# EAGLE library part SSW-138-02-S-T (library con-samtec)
THROUGH-HOLE .025" SQ POST SOCKET Source: Samtec SSW.pdf
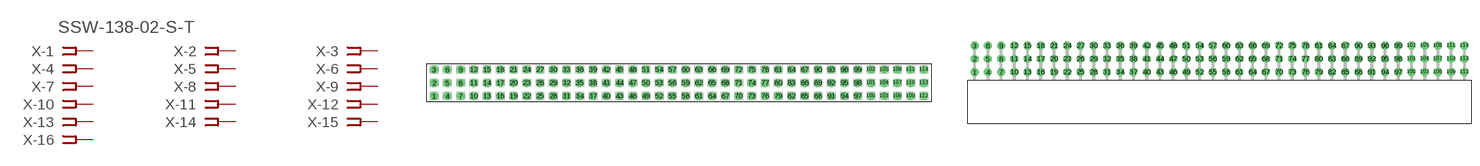
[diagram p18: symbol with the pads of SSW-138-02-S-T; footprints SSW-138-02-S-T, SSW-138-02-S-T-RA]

Designator prefix X; gates -1=FPINV -2=FPIN -3=FPIN -4=FPIN -5=FPIN -6=FPIN -7=FPIN -8=FPIN -9=FPIN -10=FPIN -11=FPIN -12=FPIN -13=FPIN -14=FPIN -15=FPIN -16=FPIN -17=FPIN -18=FPIN -19=FPIN -20=FPIN -21=FPIN -22=FPIN -23=FPIN -24=FPIN -25=FPIN -26=FPIN -27=FPIN -28=FPIN -29=FPIN -30=FPIN -31=FPIN -32=FPIN -33=FPIN -34=FPIN -35=FPIN -36=FPIN -37=FPIN -38=FPIN -39=FPIN -40=FPIN -41=FPIN -42=FPIN -43=FPIN -44=FPIN -45=FPIN -46=FPIN -47=FPIN -48=FPIN -49=FPIN -50=FPIN -51=FPIN -52=FPIN -53=FPIN -54=FPIN -55=FPIN -56=FPIN -57=FPIN -58=FPIN -59=FPIN -60=FPIN -61=FPIN -62=FPIN -63=FPIN -64=FPIN -65=FPIN -66=FPIN -67=FPIN -68=FPIN -69=FPIN -70=FPIN -71=FPIN -72=FPIN -73=FPIN -74=FPIN -75=FPIN -76=FPIN -77=FPIN -78=FPIN -79=FPIN -80=FPIN -81=FPIN -82=FPIN -83=FPIN -84=FPIN -85=FPIN -86=FPIN -87=FPIN -88=FPIN -89=FPIN -90=FPIN -91=FPIN -92=FPIN -93=FPIN -94=FPIN -95=FPIN -96=FPIN -97=FPIN -98=FPIN -99=FPIN -100=FPIN -101=FPIN -102=FPIN -103=FPIN -104=FPIN -105=FPIN -106=FPIN -107=FPIN -108=FPIN -109=FPIN -110=FPIN -111=FPIN -112=FPIN -113=FPIN -114=FPIN

## SSW-138-02-S-T (MPN: SSW-138-02-S-T; OC_FARNELL: unknown; OC_NEWARK: 83P1198)  [SSW-138-02-S-T]
1  -1:1  pas
2  -2:1  pas
3  -3:1  pas
4  -4:1  pas
5  -5:1  pas
6  -6:1  pas
7  -7:1  pas
8  -8:1  pas
9  -9:1  pas
10  -10:1  pas
11  -11:1  pas
12  -12:1  pas
13  -13:1  pas
14  -14:1  pas
15  -15:1  pas
16  -16:1  pas
17  -17:1  pas
18  -18:1  pas
19  -19:1  pas
20  -20:1  pas
21  -21:1  pas
22  -22:1  pas
23  -23:1  pas
24  -24:1  pas
25  -25:1  pas
26  -26:1  pas
27  -27:1  pas
28  -28:1  pas
29  -29:1  pas
30  -30:1  pas
31  -31:1  pas
32  -32:1  pas
33  -33:1  pas
34  -34:1  pas
35  -35:1  pas
36  -36:1  pas
37  -37:1  pas
38  -38:1  pas
39  -39:1  pas
40  -40:1  pas
41  -41:1  pas
42  -42:1  pas
43  -43:1  pas
44  -44:1  pas
45  -45:1  pas
46  -46:1  pas
47  -47:1  pas
48  -48:1  pas
49  -49:1  pas
50  -50:1  pas
51  -51:1  pas
52  -52:1  pas
53  -53:1  pas
54  -54:1  pas
55  -55:1  pas
56  -56:1  pas
57  -57:1  pas
58  -58:1  pas
59  -59:1  pas
60  -60:1  pas
61  -61:1  pas
62  -62:1  pas
63  -63:1  pas
64  -64:1  pas
65  -65:1  pas
66  -66:1  pas
67  -67:1  pas
68  -68:1  pas
69  -69:1  pas
70  -70:1  pas
71  -71:1  pas
72  -72:1  pas
73  -73:1  pas
74  -74:1  pas
75  -75:1  pas
76  -76:1  pas
77  -77:1  pas
78  -78:1  pas
79  -79:1  pas
80  -80:1  pas
81  -81:1  pas
82  -82:1  pas
83  -83:1  pas
84  -84:1  pas
85  -85:1  pas
86  -86:1  pas
87  -87:1  pas
88  -88:1  pas
89  -89:1  pas
90  -90:1  pas
91  -91:1  pas
92  -92:1  pas
93  -93:1  pas
94  -94:1  pas
95  -95:1  pas
96  -96:1  pas
97  -97:1  pas
98  -98:1  pas
99  -99:1  pas
100  -100:1  pas
101  -101:1  pas
102  -102:1  pas
103  -103:1  pas
104  -104:1  pas
105  -105:1  pas
106  -106:1  pas
107  -107:1  pas
108  -108:1  pas
109  -109:1  pas
110  -110:1  pas
111  -111:1  pas
112  -112:1  pas
113  -113:1  pas
114  -114:1  pas

## SSW-138-02-S-TRA (OC_FARNELL: unknown; OC_NEWARK: unknown)  [SSW-138-02-S-T-RA]
Pads as for SSW-138-02-S-T

## Footprint SSW-138-02-S-T (pad centres in mm)
THROUGH-HOLE .025" SQ POST SOCKET Source: Samtec SSW.pdf
drill 1 pad 1.5 octagon: 1 -46.99,-2.54; 2 -46.99,0; 3 -46.99,2.54; 4 -44.45,-2.54; 5 -44.45,0; 6 -44.45,2.54; 7 -41.91,-2.54; 8 -41.91,0; 9 -41.91,2.54; 10 -39.37,-2.54; 11 -39.37,0; 12 -39.37,2.54; 13 -36.83,-2.54; 14 -36.83,0; 15 -36.83,2.54; 16 -34.29,-2.54; 17 -34.29,0; 18 -34.29,2.54; 19 -31.75,-2.54; 20 -31.75,0; 21 -31.75,2.54; 22 -29.21,-2.54; 23 -29.21,0; 24 -29.21,2.54; 25 -26.67,-2.54; 26 -26.67,0; 27 -26.67,2.54; 28 -24.13,-2.54; 29 -24.13,0; 30 -24.13,2.54; 31 -21.59,-2.54; 32 -21.59,0; 33 -21.59,2.54; 34 -19.05,-2.54; 35 -19.05,0; 36 -19.05,2.54; 37 -16.51,-2.54; 38 -16.51,0; 39 -16.51,2.54; 40 -13.97,-2.54; 41 -13.97,0; 42 -13.97,2.54; 43 -11.43,-2.54; 44 -11.43,0; 45 -11.43,2.54; 46 -8.89,-2.54; 47 -8.89,0; 48 -8.89,2.54; 49 -6.35,-2.54; 50 -6.35,0; 51 -6.35,2.54; 52 -3.81,-2.54; 53 -3.81,0; 54 -3.81,2.54; 55 -1.27,-2.54; 56 -1.27,0; 57 -1.27,2.54; 58 1.27,-2.54; 59 1.27,0; 60 1.27,2.54; 61 3.81,-2.54; 62 3.81,0; 63 3.81,2.54; 64 6.35,-2.54; 65 6.35,0; 66 6.35,2.54; 67 8.89,-2.54; 68 8.89,0; 69 8.89,2.54; 70 11.43,-2.54; 71 11.43,0; 72 11.43,2.54; 73 13.97,-2.54; 74 13.97,0; 75 13.97,2.54; 76 16.51,-2.54; 77 16.51,0; 78 16.51,2.54; 79 19.05,-2.54; 80 19.05,0; 81 19.05,2.54; 82 21.59,-2.54; 83 21.59,0; 84 21.59,2.54; 85 24.13,-2.54; 86 24.13,0; 87 24.13,2.54; 88 26.67,-2.54; 89 26.67,0; 90 26.67,2.54; 91 29.21,-2.54; 92 29.21,0; 93 29.21,2.54; 94 31.75,-2.54; 95 31.75,0; 96 31.75,2.54; 97 34.29,-2.54; 98 34.29,0; 99 34.29,2.54; 100 36.83,-2.54; 101 36.83,0; 102 36.83,2.54; 103 39.37,-2.54; 104 39.37,0; 105 39.37,2.54; 106 41.91,-2.54; 107 41.91,0; 108 41.91,2.54; 109 44.45,-2.54; 110 44.45,0; 111 44.45,2.54; 112 46.99,-2.54; 113 46.99,0; 114 46.99,2.54

## Footprint SSW-138-02-S-T-RA (pad centres in mm)
THROUGH-HOLE .025" SQ POST SOCKET Source: Samtec SSW.pdf
drill 1 pad 1.5 octagon: 1 -46.99,1.524; 2 -46.99,4.064; 3 -46.99,6.604; 4 -44.45,1.524; 5 -44.45,4.064; 6 -44.45,6.604; 7 -41.91,1.524; 8 -41.91,4.064; 9 -41.91,6.604; 10 -39.37,1.524; 11 -39.37,4.064; 12 -39.37,6.604; 13 -36.83,1.524; 14 -36.83,4.064; 15 -36.83,6.604; 16 -34.29,1.524; 17 -34.29,4.064; 18 -34.29,6.604; 19 -31.75,1.524; 20 -31.75,4.064; 21 -31.75,6.604; 22 -29.21,1.524; 23 -29.21,4.064; 24 -29.21,6.604; 25 -26.67,1.524; 26 -26.67,4.064; 27 -26.67,6.604; 28 -24.13,1.524; 29 -24.13,4.064; 30 -24.13,6.604; 31 -21.59,1.524; 32 -21.59,4.064; 33 -21.59,6.604; 34 -19.05,1.524; 35 -19.05,4.064; 36 -19.05,6.604; 37 -16.51,1.524; 38 -16.51,4.064; 39 -16.51,6.604; 40 -13.97,1.524; 41 -13.97,4.064; 42 -13.97,6.604; 43 -11.43,1.524; 44 -11.43,4.064; 45 -11.43,6.604; 46 -8.89,1.524; 47 -8.89,4.064; 48 -8.89,6.604; 49 -6.35,1.524; 50 -6.35,4.064; 51 -6.35,6.604; 52 -3.81,1.524; 53 -3.81,4.064; 54 -3.81,6.604; 55 -1.27,1.524; 56 -1.27,4.064; 57 -1.27,6.604; 58 1.27,1.524; 59 1.27,4.064; 60 1.27,6.604; 61 3.81,1.524; 62 3.81,4.064; 63 3.81,6.604; 64 6.35,1.524; 65 6.35,4.064; 66 6.35,6.604; 67 8.89,1.524; 68 8.89,4.064; 69 8.89,6.604; 70 11.43,1.524; 71 11.43,4.064; 72 11.43,6.604; 73 13.97,1.524; 74 13.97,4.064; 75 13.97,6.604; 76 16.51,1.524; 77 16.51,4.064; 78 16.51,6.604; 79 19.05,1.524; 80 19.05,4.064; 81 19.05,6.604; 82 21.59,1.524; 83 21.59,4.064; 84 21.59,6.604; 85 24.13,1.524; 86 24.13,4.064; 87 24.13,6.604; 88 26.67,1.524; 89 26.67,4.064; 90 26.67,6.604; 91 29.21,1.524; 92 29.21,4.064; 93 29.21,6.604; 94 31.75,1.524; 95 31.75,4.064; 96 31.75,6.604; 97 34.29,1.524; 98 34.29,4.064; 99 34.29,6.604; 100 36.83,1.524; 101 36.83,4.064; 102 36.83,6.604; 103 39.37,1.524; 104 39.37,4.064; 105 39.37,6.604; 106 41.91,1.524; 107 41.91,4.064; 108 41.91,6.604; 109 44.45,1.524; 110 44.45,4.064; 111 44.45,6.604; 112 46.99,1.524; 113 46.99,4.064; 114 46.99,6.604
